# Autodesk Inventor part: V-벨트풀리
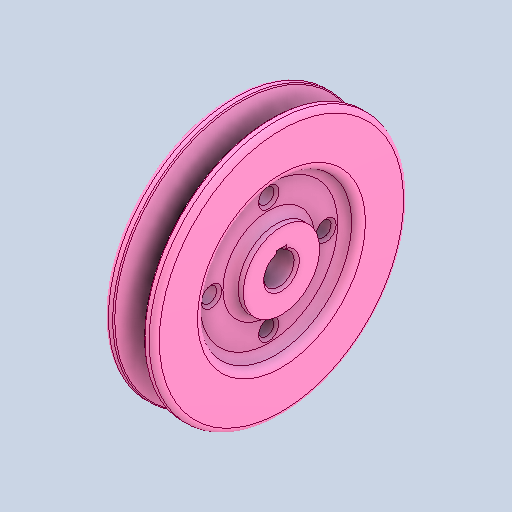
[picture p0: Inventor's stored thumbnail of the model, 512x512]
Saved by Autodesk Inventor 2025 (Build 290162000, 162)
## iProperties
Created: 2024-07
Part Number: V-벨트풀리
Material: 강철, 연강
Document SubType Name: Modeling
Designer: myung
Density: 7.86 g/cm^3
Appearance: 기본값
Author: jhkim
Sending System: Autodesk Inventor 2025
Preprocessor: ST-DEVELOPER v20
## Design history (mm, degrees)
feature "솔리드1"
node "솔리드2"
